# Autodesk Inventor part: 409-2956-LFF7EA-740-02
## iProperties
Created: 2010-06
Part Number: 409-2956-LFF7EA-740-02
Material: Sch40 CS PIPE SEAMLESS
Description: PIPE
Document SubType Name: Modeling
Designer: S. Boerckel
Engineer: Steve Boerckel
Mass: 12657.4 g
Surface Area: 5397.99 cm^2
Volume: 1612.41 cm^3
Density: 7.85 g/cm^3
Cost Center: 4"
SMR: =<COST CENTER> - <Material>
Length: 31.000 in
Title: 4"
Author: S. Boerckel
Revision Number: B
Subject: DEMIN WATER FORWARDING PUMP SKID-7EA
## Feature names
1. Extrusion1
